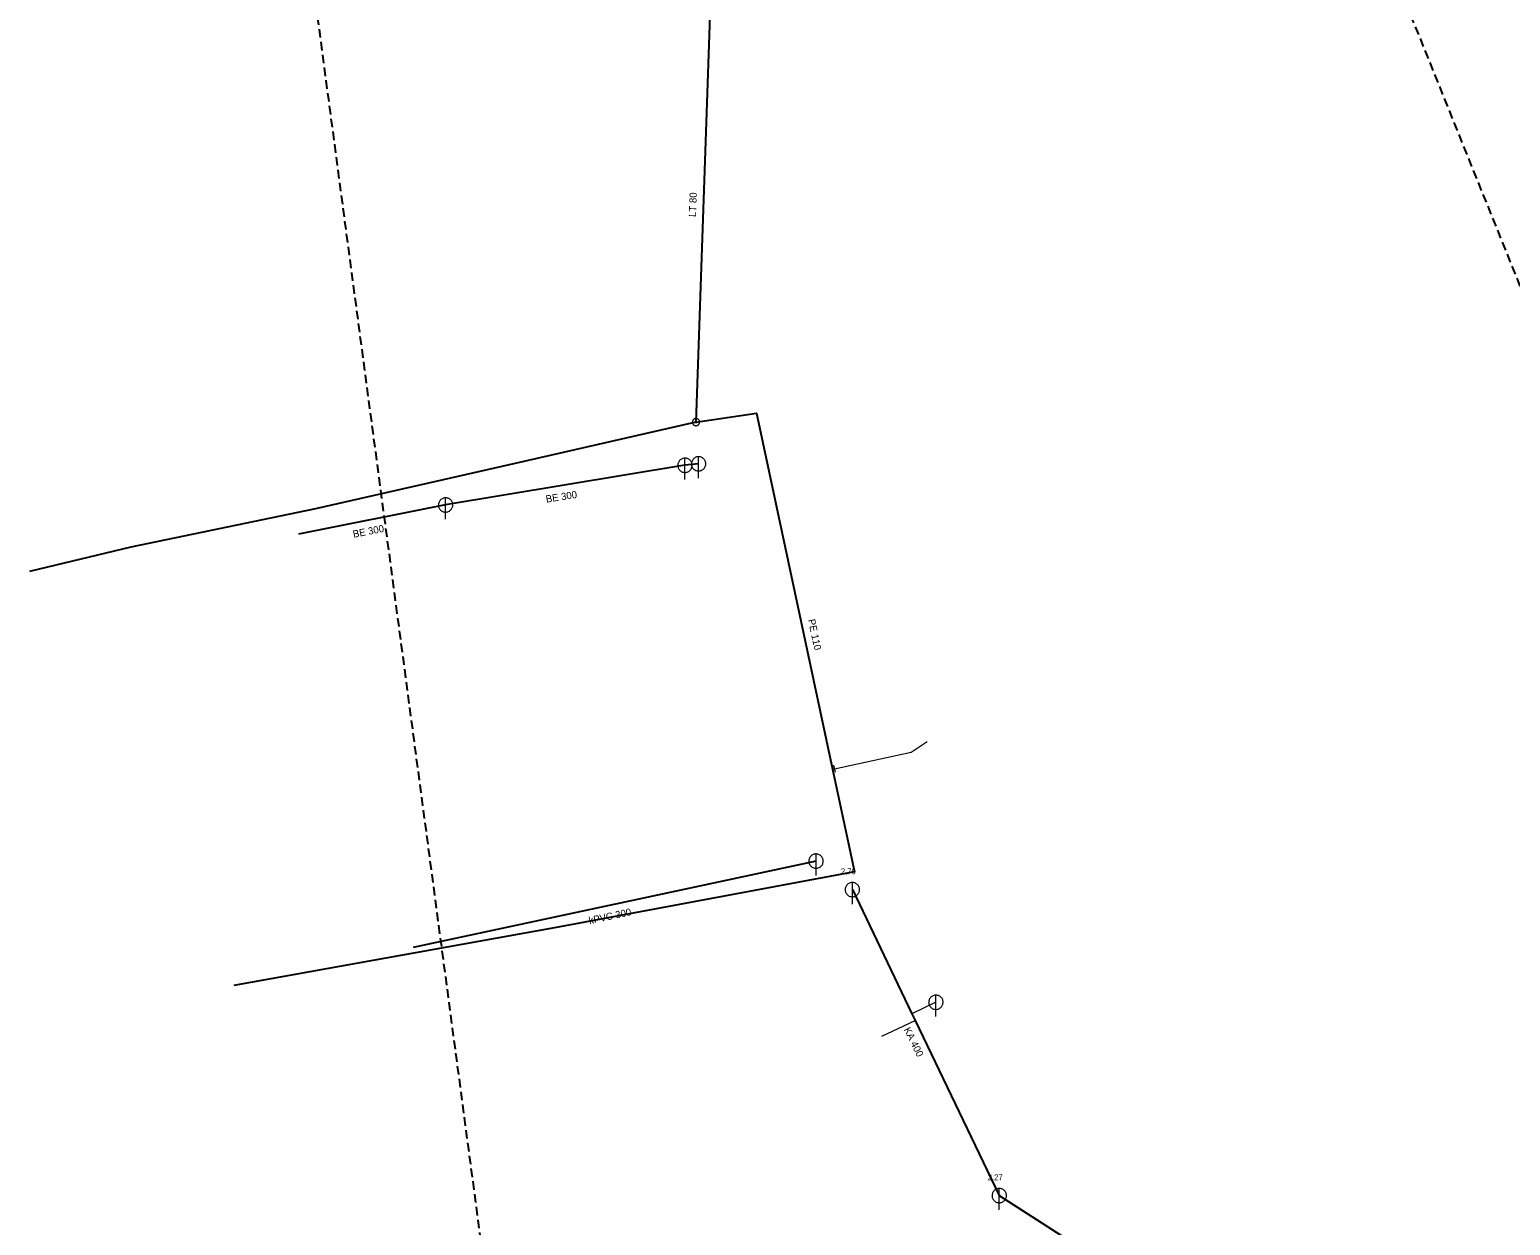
# Model space of a CAD drawing. Extents: x -682839 to -682312, y -994645 to -993949.
# Drawn here: x -682756.4 to -682550, y -994475 to -994308.3 of the extents above; entities that cross this region are included whole.
import ezdxf

# ---------------------------------------------------------------- set-up
doc = ezdxf.new("R2010")
doc.units = 0
doc.header["$LTSCALE"] = 0.4
doc.linetypes.add('MEDIUM_DASHED', pattern=[4.5, 3, -1.5])
doc.layers.add('1', color=7, linetype='Continuous')
for name, color, linetype, lineweight in [('11', 7, 'Continuous', 13), ('13', 7, 'Continuous', 13), ('14', 7, 'Continuous', 25), ('17', 7, 'Continuous', 25), ('22', 7, 'Continuous', 13), ('34', 7, 'Continuous', 13), ('47', 7, 'Continuous', 13), ('63', 7, 'MEDIUM_DASHED', 25)]:
    doc.layers.add(name, color=color, linetype=linetype, lineweight=lineweight)

msp = doc.modelspace()

# ---------------------------------------------------------------- linework, layer by layer
at = {"layer": '11'}
for p, q in [((-682630.079, -994443.87), (-682633.41, -994445.469)), ((-682637.609, -994448.609), (-682632.98, -994446.39))]:
    msp.add_line(p, q, dxfattribs=at)
at = {"layer": '13'}
msp.add_lwpolyline([(-682644.218, -994411.319), (-682633.52, -994409.01), (-682631.308, -994407.528)], dxfattribs=at)
at = {"layer": '14'}
for p, q in [((-682665.039, -994369.03), (-682698.39, -994374.559)), ((-682663.14, -994368.829), (-682665.039, -994369.03)), ((-682698.39, -994374.559), (-682718.91, -994378.64)), ((-682646.778, -994424.191), (-682702.899, -994436.208)), ((-682621.25, -994470.809), (-682599.32, -994484.859))]:
    msp.add_line(p, q, dxfattribs=at)
at = {"layer": '14', "lineweight": 13}
msp.add_line((-682644.476, -994411.376), (-682644.218, -994411.319), dxfattribs=at)
at = {"layer": '14'}
msp.add_lwpolyline([(-682641.719, -994428.17), (-682633.41, -994445.469), (-682632.98, -994446.39), (-682621.25, -994470.809)], dxfattribs=at)
at = {"layer": '17'}
for points in [[(-682661.734, -994293.879), (-682661.579, -994297.93), (-682661.366, -994300.932), (-682663.509, -994363.011)], [(-682663.509, -994363.011), (-682687.48, -994368.517), (-682716.535, -994375.094), (-682742.25, -994380.447), (-682756.353, -994383.813)], [(-682663.509, -994363.011), (-682655.059, -994361.75), (-682644.476, -994411.376), (-682641.425, -994425.68), (-682683.232, -994433.484), (-682727.881, -994441.517)]]:
    msp.add_lwpolyline(points, dxfattribs=at)
at = {"layer": '22'}
for p, q in [((-682665.04, -994371.03), (-682665.039, -994368.03)), ((-682663.14, -994370.83), (-682663.139, -994367.83)), ((-682698.39, -994376.56), (-682698.389, -994373.56)), ((-682646.779, -994426.191), (-682646.778, -994423.191)), ((-682641.719, -994430.17), (-682641.718, -994427.17)), ((-682630.079, -994445.87), (-682630.078, -994442.87)), ((-682621.25, -994472.809), (-682621.249, -994469.809))]:
    msp.add_line(p, q, dxfattribs=at)
for points in [[(-682664.04, -994369.03), (-682664.045, -994368.921), (-682664.063, -994368.813), (-682664.093, -994368.707), (-682664.133, -994368.606), (-682664.185, -994368.509), (-682664.247, -994368.419), (-682664.319, -994368.336), (-682664.399, -994368.262), (-682664.487, -994368.196), (-682664.581, -994368.141), (-682664.681, -994368.096), (-682664.786, -994368.063), (-682664.893, -994368.041), (-682665.002, -994368.031), (-682665.112, -994368.033), (-682665.22, -994368.047), (-682665.327, -994368.072), (-682665.43, -994368.109), (-682665.528, -994368.158), (-682665.62, -994368.216), (-682665.706, -994368.285), (-682665.783, -994368.362), (-682665.852, -994368.448), (-682665.911, -994368.54), (-682665.959, -994368.638), (-682665.996, -994368.741), (-682666.022, -994368.848), (-682666.036, -994368.956), (-682666.039, -994369.066), (-682666.029, -994369.175), (-682666.008, -994369.282), (-682665.974, -994369.386), (-682665.93, -994369.486), (-682665.875, -994369.581), (-682665.809, -994369.669), (-682665.735, -994369.749), (-682665.652, -994369.821), (-682665.562, -994369.883), (-682665.466, -994369.935), (-682665.364, -994369.976), (-682665.259, -994370.006), (-682665.151, -994370.024), (-682665.041, -994370.03), (-682664.932, -994370.024), (-682664.824, -994370.006), (-682664.719, -994369.977), (-682664.617, -994369.936), (-682664.52, -994369.884), (-682664.43, -994369.822), (-682664.347, -994369.751), (-682664.272, -994369.671), (-682664.207, -994369.583), (-682664.151, -994369.489), (-682664.107, -994369.389), (-682664.073, -994369.285), (-682664.051, -994369.177), (-682664.041, -994369.068)], [(-682662.14, -994368.83), (-682662.145, -994368.721), (-682662.163, -994368.613), (-682662.193, -994368.507), (-682662.233, -994368.406), (-682662.285, -994368.309), (-682662.347, -994368.219), (-682662.419, -994368.136), (-682662.499, -994368.062), (-682662.587, -994367.996), (-682662.681, -994367.941), (-682662.781, -994367.896), (-682662.886, -994367.863), (-682662.993, -994367.841), (-682663.102, -994367.831), (-682663.212, -994367.833), (-682663.32, -994367.847), (-682663.427, -994367.872), (-682663.53, -994367.909), (-682663.628, -994367.958), (-682663.72, -994368.016), (-682663.806, -994368.085), (-682663.883, -994368.162), (-682663.952, -994368.248), (-682664.011, -994368.34), (-682664.059, -994368.438), (-682664.096, -994368.541), (-682664.122, -994368.648), (-682664.136, -994368.756), (-682664.139, -994368.866), (-682664.129, -994368.975), (-682664.108, -994369.082), (-682664.074, -994369.186), (-682664.03, -994369.286), (-682663.975, -994369.381), (-682663.909, -994369.469), (-682663.835, -994369.549), (-682663.752, -994369.621), (-682663.662, -994369.683), (-682663.566, -994369.735), (-682663.464, -994369.776), (-682663.359, -994369.806), (-682663.251, -994369.824), (-682663.141, -994369.83), (-682663.032, -994369.824), (-682662.924, -994369.806), (-682662.819, -994369.777), (-682662.717, -994369.736), (-682662.62, -994369.684), (-682662.53, -994369.622), (-682662.447, -994369.551), (-682662.372, -994369.471), (-682662.307, -994369.383), (-682662.251, -994369.289), (-682662.207, -994369.189), (-682662.173, -994369.085), (-682662.151, -994368.977), (-682662.141, -994368.868)], [(-682697.39, -994374.56), (-682697.395, -994374.451), (-682697.413, -994374.343), (-682697.443, -994374.237), (-682697.483, -994374.136), (-682697.535, -994374.039), (-682697.597, -994373.949), (-682697.669, -994373.866), (-682697.749, -994373.792), (-682697.837, -994373.726), (-682697.931, -994373.671), (-682698.031, -994373.626), (-682698.136, -994373.593), (-682698.243, -994373.571), (-682698.352, -994373.561), (-682698.462, -994373.563), (-682698.57, -994373.577), (-682698.677, -994373.602), (-682698.78, -994373.639), (-682698.878, -994373.688), (-682698.97, -994373.746), (-682699.056, -994373.815), (-682699.133, -994373.892), (-682699.202, -994373.978), (-682699.261, -994374.07), (-682699.309, -994374.168), (-682699.346, -994374.271), (-682699.372, -994374.378), (-682699.386, -994374.486), (-682699.389, -994374.596), (-682699.379, -994374.705), (-682699.358, -994374.812), (-682699.324, -994374.916), (-682699.28, -994375.016), (-682699.225, -994375.111), (-682699.159, -994375.199), (-682699.085, -994375.279), (-682699.002, -994375.351), (-682698.912, -994375.413), (-682698.816, -994375.465), (-682698.714, -994375.506), (-682698.609, -994375.536), (-682698.501, -994375.554), (-682698.391, -994375.56), (-682698.282, -994375.554), (-682698.174, -994375.536), (-682698.069, -994375.507), (-682697.967, -994375.466), (-682697.87, -994375.414), (-682697.78, -994375.352), (-682697.697, -994375.281), (-682697.622, -994375.201), (-682697.557, -994375.113), (-682697.501, -994375.019), (-682697.457, -994374.919), (-682697.423, -994374.815), (-682697.401, -994374.707), (-682697.391, -994374.598)], [(-682645.779, -994424.191), (-682645.784, -994424.082), (-682645.802, -994423.974), (-682645.832, -994423.868), (-682645.872, -994423.767), (-682645.924, -994423.67), (-682645.986, -994423.58), (-682646.058, -994423.497), (-682646.138, -994423.423), (-682646.226, -994423.357), (-682646.32, -994423.302), (-682646.42, -994423.257), (-682646.525, -994423.224), (-682646.632, -994423.202), (-682646.741, -994423.192), (-682646.851, -994423.194), (-682646.959, -994423.208), (-682647.066, -994423.233), (-682647.169, -994423.27), (-682647.267, -994423.319), (-682647.359, -994423.377), (-682647.445, -994423.446), (-682647.522, -994423.523), (-682647.591, -994423.609), (-682647.65, -994423.701), (-682647.698, -994423.799), (-682647.735, -994423.902), (-682647.761, -994424.009), (-682647.775, -994424.117), (-682647.778, -994424.227), (-682647.768, -994424.336), (-682647.747, -994424.443), (-682647.713, -994424.547), (-682647.669, -994424.647), (-682647.614, -994424.742), (-682647.548, -994424.83), (-682647.474, -994424.91), (-682647.391, -994424.982), (-682647.301, -994425.044), (-682647.205, -994425.096), (-682647.103, -994425.137), (-682646.998, -994425.167), (-682646.89, -994425.185), (-682646.78, -994425.191), (-682646.671, -994425.185), (-682646.563, -994425.167), (-682646.458, -994425.138), (-682646.356, -994425.097), (-682646.259, -994425.045), (-682646.169, -994424.983), (-682646.086, -994424.912), (-682646.011, -994424.832), (-682645.946, -994424.744), (-682645.89, -994424.65), (-682645.846, -994424.55), (-682645.812, -994424.446), (-682645.79, -994424.338), (-682645.78, -994424.229)], [(-682640.719, -994428.17), (-682640.724, -994428.061), (-682640.742, -994427.953), (-682640.772, -994427.847), (-682640.812, -994427.746), (-682640.864, -994427.649), (-682640.926, -994427.559), (-682640.998, -994427.476), (-682641.078, -994427.402), (-682641.166, -994427.336), (-682641.26, -994427.281), (-682641.36, -994427.236), (-682641.465, -994427.203), (-682641.572, -994427.181), (-682641.681, -994427.171), (-682641.791, -994427.173), (-682641.899, -994427.187), (-682642.006, -994427.212), (-682642.109, -994427.249), (-682642.207, -994427.298), (-682642.299, -994427.356), (-682642.385, -994427.425), (-682642.462, -994427.502), (-682642.531, -994427.588), (-682642.59, -994427.68), (-682642.638, -994427.778), (-682642.675, -994427.881), (-682642.701, -994427.988), (-682642.715, -994428.096), (-682642.718, -994428.206), (-682642.708, -994428.315), (-682642.687, -994428.422), (-682642.653, -994428.526), (-682642.609, -994428.626), (-682642.554, -994428.721), (-682642.488, -994428.809), (-682642.414, -994428.889), (-682642.331, -994428.961), (-682642.241, -994429.023), (-682642.145, -994429.075), (-682642.043, -994429.116), (-682641.938, -994429.146), (-682641.83, -994429.164), (-682641.72, -994429.17), (-682641.611, -994429.164), (-682641.503, -994429.146), (-682641.398, -994429.117), (-682641.296, -994429.076), (-682641.199, -994429.024), (-682641.109, -994428.962), (-682641.026, -994428.891), (-682640.951, -994428.811), (-682640.886, -994428.723), (-682640.83, -994428.629), (-682640.786, -994428.529), (-682640.752, -994428.425), (-682640.73, -994428.317), (-682640.72, -994428.208)], [(-682629.079, -994443.87), (-682629.084, -994443.761), (-682629.102, -994443.653), (-682629.132, -994443.547), (-682629.172, -994443.446), (-682629.224, -994443.349), (-682629.286, -994443.259), (-682629.358, -994443.176), (-682629.438, -994443.102), (-682629.526, -994443.036), (-682629.62, -994442.981), (-682629.72, -994442.936), (-682629.825, -994442.903), (-682629.932, -994442.881), (-682630.041, -994442.871), (-682630.151, -994442.873), (-682630.259, -994442.887), (-682630.366, -994442.912), (-682630.469, -994442.949), (-682630.567, -994442.998), (-682630.659, -994443.056), (-682630.745, -994443.125), (-682630.822, -994443.202), (-682630.891, -994443.288), (-682630.95, -994443.38), (-682630.998, -994443.478), (-682631.035, -994443.581), (-682631.061, -994443.688), (-682631.075, -994443.796), (-682631.078, -994443.906), (-682631.068, -994444.015), (-682631.047, -994444.122), (-682631.013, -994444.226), (-682630.969, -994444.326), (-682630.914, -994444.421), (-682630.848, -994444.509), (-682630.774, -994444.589), (-682630.691, -994444.661), (-682630.601, -994444.723), (-682630.505, -994444.775), (-682630.403, -994444.816), (-682630.298, -994444.846), (-682630.19, -994444.864), (-682630.08, -994444.87), (-682629.971, -994444.864), (-682629.863, -994444.846), (-682629.758, -994444.817), (-682629.656, -994444.776), (-682629.559, -994444.724), (-682629.469, -994444.662), (-682629.386, -994444.591), (-682629.311, -994444.511), (-682629.246, -994444.423), (-682629.19, -994444.329), (-682629.146, -994444.229), (-682629.112, -994444.125), (-682629.09, -994444.017), (-682629.08, -994443.908)], [(-682620.25, -994470.809), (-682620.255, -994470.7), (-682620.273, -994470.592), (-682620.303, -994470.486), (-682620.343, -994470.385), (-682620.395, -994470.288), (-682620.457, -994470.198), (-682620.529, -994470.115), (-682620.609, -994470.041), (-682620.697, -994469.975), (-682620.791, -994469.92), (-682620.891, -994469.875), (-682620.996, -994469.842), (-682621.103, -994469.82), (-682621.212, -994469.81), (-682621.322, -994469.812), (-682621.43, -994469.826), (-682621.537, -994469.851), (-682621.64, -994469.888), (-682621.738, -994469.937), (-682621.83, -994469.995), (-682621.916, -994470.064), (-682621.993, -994470.141), (-682622.062, -994470.227), (-682622.121, -994470.319), (-682622.169, -994470.417), (-682622.206, -994470.52), (-682622.232, -994470.627), (-682622.246, -994470.735), (-682622.249, -994470.845), (-682622.239, -994470.954), (-682622.218, -994471.061), (-682622.184, -994471.165), (-682622.14, -994471.265), (-682622.085, -994471.36), (-682622.019, -994471.448), (-682621.945, -994471.528), (-682621.862, -994471.6), (-682621.772, -994471.662), (-682621.676, -994471.714), (-682621.574, -994471.755), (-682621.469, -994471.785), (-682621.361, -994471.803), (-682621.251, -994471.809), (-682621.142, -994471.803), (-682621.034, -994471.785), (-682620.929, -994471.756), (-682620.827, -994471.715), (-682620.73, -994471.663), (-682620.64, -994471.601), (-682620.557, -994471.53), (-682620.482, -994471.45), (-682620.417, -994471.362), (-682620.361, -994471.268), (-682620.317, -994471.168), (-682620.283, -994471.064), (-682620.261, -994470.956), (-682620.251, -994470.847)]]:
    msp.add_lwpolyline(points, close=True, dxfattribs=at)
at = {"layer": '34'}
msp.add_line((-682644.326, -994410.83), (-682644.11, -994411.807), dxfattribs=at)
at = {"layer": '47'}
for points in [[(-682663.009, -994363.011), (-682663.012, -994362.959), (-682663.02, -994362.907), (-682663.034, -994362.857), (-682663.051, -994362.808), (-682663.076, -994362.761), (-682663.105, -994362.717), (-682663.137, -994362.677), (-682663.174, -994362.64), (-682663.215, -994362.607), (-682663.259, -994362.578), (-682663.306, -994362.554), (-682663.355, -994362.536), (-682663.404, -994362.522), (-682663.456, -994362.514), (-682663.509, -994362.511), (-682663.561, -994362.514), (-682663.613, -994362.522), (-682663.664, -994362.536), (-682663.712, -994362.554), (-682663.759, -994362.578), (-682663.803, -994362.607), (-682663.843, -994362.64), (-682663.88, -994362.677), (-682663.914, -994362.717), (-682663.941, -994362.761), (-682663.966, -994362.808), (-682663.985, -994362.857), (-682663.997, -994362.907), (-682664.005, -994362.959), (-682664.009, -994363.011), (-682664.005, -994363.063), (-682663.997, -994363.115), (-682663.985, -994363.166), (-682663.966, -994363.214), (-682663.941, -994363.261), (-682663.914, -994363.305), (-682663.88, -994363.346), (-682663.843, -994363.383), (-682663.803, -994363.416), (-682663.759, -994363.444), (-682663.712, -994363.468), (-682663.664, -994363.487), (-682663.613, -994363.5), (-682663.561, -994363.508), (-682663.509, -994363.511), (-682663.456, -994363.508), (-682663.404, -994363.5), (-682663.355, -994363.487), (-682663.306, -994363.468), (-682663.259, -994363.444), (-682663.215, -994363.416), (-682663.174, -994363.383), (-682663.137, -994363.346), (-682663.105, -994363.305), (-682663.076, -994363.261), (-682663.051, -994363.214), (-682663.034, -994363.166), (-682663.02, -994363.115), (-682663.012, -994363.063)], [(-682663.426, -994363.011), (-682663.426, -994363.002), (-682663.429, -994362.994), (-682663.431, -994362.986), (-682663.434, -994362.978), (-682663.438, -994362.97), (-682663.443, -994362.963), (-682663.448, -994362.956), (-682663.453, -994362.95), (-682663.461, -994362.945), (-682663.468, -994362.94), (-682663.475, -994362.936), (-682663.483, -994362.933), (-682663.492, -994362.931), (-682663.5, -994362.929), (-682663.509, -994362.929), (-682663.517, -994362.929), (-682663.526, -994362.931), (-682663.534, -994362.933), (-682663.542, -994362.936), (-682663.549, -994362.94), (-682663.556, -994362.945), (-682663.564, -994362.95), (-682663.57, -994362.956), (-682663.576, -994362.963), (-682663.58, -994362.97), (-682663.583, -994362.978), (-682663.587, -994362.986), (-682663.588, -994362.994), (-682663.591, -994363.002), (-682663.591, -994363.011), (-682663.591, -994363.02), (-682663.588, -994363.028), (-682663.587, -994363.036), (-682663.583, -994363.044), (-682663.58, -994363.052), (-682663.576, -994363.059), (-682663.57, -994363.066), (-682663.564, -994363.072), (-682663.556, -994363.078), (-682663.549, -994363.082), (-682663.542, -994363.086), (-682663.534, -994363.089), (-682663.526, -994363.091), (-682663.517, -994363.093), (-682663.509, -994363.093), (-682663.5, -994363.093), (-682663.492, -994363.091), (-682663.483, -994363.089), (-682663.475, -994363.086), (-682663.468, -994363.082), (-682663.461, -994363.078), (-682663.453, -994363.072), (-682663.448, -994363.066), (-682663.443, -994363.059), (-682663.438, -994363.052), (-682663.434, -994363.044), (-682663.431, -994363.036), (-682663.429, -994363.028), (-682663.426, -994363.02)]]:
    msp.add_lwpolyline(points, close=True, dxfattribs=at)
at = {"layer": '63'}
msp.add_lwpolyline([(-682494.62, -994477.955), (-682564.4, -994570.065), (-682564.4, -994570.065), (-682684.423, -994544.944), (-682684.423, -994544.944), (-682751.412, -994042.525), (-682751.412, -994042.525), (-682670.466, -994042.525), (-682670.466, -994042.525)], close=True, dxfattribs=at)

# ---------------------------------------------------------------- texts
at = {"layer": '1'}
for s, rotation, p in [('LT 80 ', 88, (-682663.508, -994334.435)), ('BE 300', 9, (-682684.349, -994374.244)), ('BE 300', 11, (-682711.204, -994379.131)), ('PE 110', 282, (-682647.903, -994390.575)), ('kPVC 300', 12, (-682678.334, -994432.978)), ('KA 400', 296, (-682634.578, -994447.646))]:
    msp.add_text(s, height=1, rotation=rotation, dxfattribs=at).set_placement(p)
for s, p in [('2,70', (-682643.319, -994426.017)), ('2,27', (-682622.85, -994468.657))]:
    msp.add_text(s, height=0.8, dxfattribs=at).set_placement(p)

doc.saveas('drawing.dxf')
